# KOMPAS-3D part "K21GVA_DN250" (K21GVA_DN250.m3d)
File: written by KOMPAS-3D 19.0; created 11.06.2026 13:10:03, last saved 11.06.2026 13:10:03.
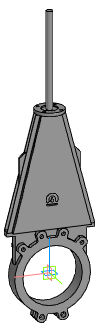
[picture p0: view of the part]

Document properties: Автор: Энергия; Полное имя файла: Z:\3.Личные\kachalov\001_3d для проектировщиков\2.5 Тип_K21GVA. Задвижка\_stp\_stp_K21GVA_DN50-DN1000_с фланцем\K21GVA_DN250.m3d

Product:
- Part/product: K21GVA_DN250

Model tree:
1. Операция без истории:1  (labels: K21GVA_DN250)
